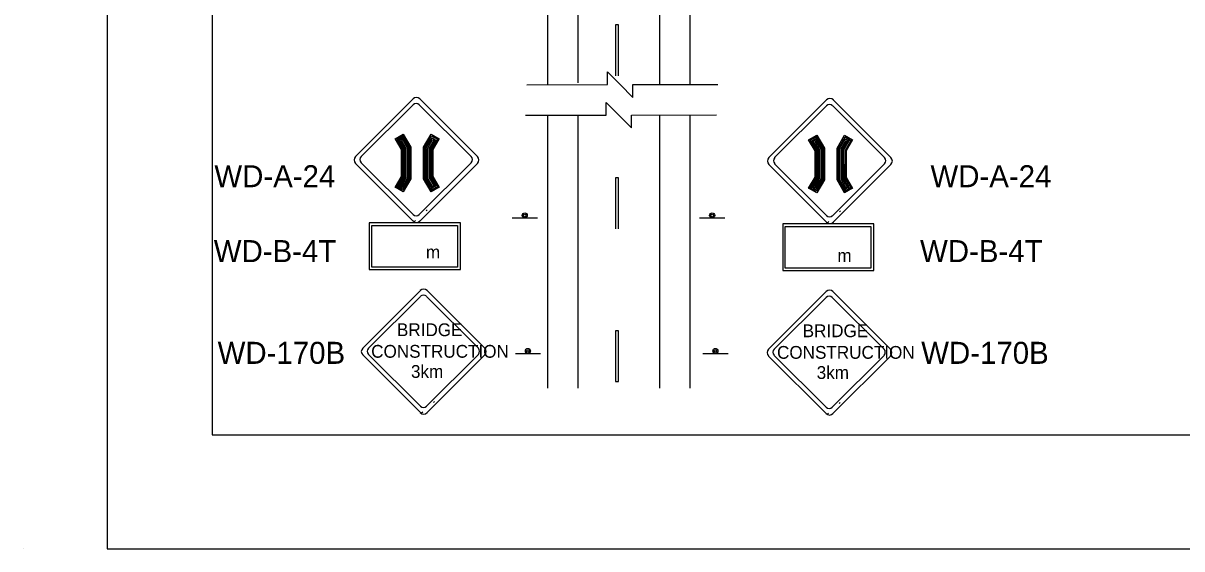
# Model space of a CAD drawing. Extents: x 2171 to 2395, y 134 to 413.
# Drawn here: x 2170.8 to 2280.9, y 133.8 to 183.7 of the extents above; entities that cross this region are included whole.
import ezdxf

# ---------------------------------------------------------------- set-up
doc = ezdxf.new("R2010")
doc.units = 0
for name, color, linetype in [('Level 1', 7, 'Continuous'), ('Level 10', 7, 'Continuous'), ('Level 2', 7, 'Continuous'), ('Level 20', 7, 'Continuous'), ('Level 44', 7, 'Continuous'), ('Level 60', 7, 'Continuous')]:
    doc.layers.add(name, color=color, linetype=linetype)

msp = doc.modelspace()

# ---------------------------------------------------------------- linework, layer by layer
at = {"layer": 'Level 10'}
for p, q in [((2223.52, 177.99), (2223.52, 287.5)), ((2231.26, 177.84), (2231.26, 284.77)), ((2223.52, 149.02), (2223.52, 174.93)), ((2231.26, 149.02), (2231.26, 174.95))]:
    msp.add_line(p, q, dxfattribs=at)
for points in [[(2203.91, 164.47), (2212.05, 164.47), (2212.05, 160.51), (2203.91, 160.51)], [(2243.19, 164.37), (2251.34, 164.37), (2251.34, 160.42), (2243.19, 160.42)]]:
    msp.add_lwpolyline(points, close=True, dxfattribs=at)
at = {"layer": 'Level 2'}
for p, q in [((2227.07, 183.5), (2227.07, 178.66)), ((2227.36, 183.5), (2227.07, 183.5)), ((2227.36, 178.66), (2227.36, 183.5)), ((2227.07, 168.99), (2227.07, 164.15)), ((2227.36, 168.99), (2227.07, 168.99)), ((2227.36, 164.15), (2227.36, 168.99)), ((2209.17, 165.95), (2209.07, 165.85)), ((2248.45, 165.86), (2248.35, 165.75)), ((2208.05, 164.94), (2207.95, 164.83)), ((2247.34, 164.84), (2247.23, 164.73)), ((2227.07, 154.47), (2227.07, 149.64)), ((2227.36, 154.47), (2227.07, 154.47)), ((2227.36, 149.64), (2227.36, 154.47)), ((2227.07, 149.64), (2227.36, 149.64)), ((2209.86, 147.76), (2209.76, 147.66)), ((2248.41, 147.66), (2248.31, 147.56)), ((2208.75, 146.74), (2208.64, 146.64)), ((2247.3, 146.65), (2247.2, 146.54))]:
    msp.add_line(p, q, dxfattribs=at)
at = {"layer": 'Level 20'}
for p, q in [((2234.16, 177.84), (2234.16, 327.61)), ((2220.62, 177.82), (2220.62, 313.63)), ((2220.62, 149.02), (2220.62, 174.93)), ((2234.16, 149.02), (2234.16, 174.95))]:
    msp.add_line(p, q, dxfattribs=at)
for points in [[(2218.63, 177.82), (2226.29, 177.83), (2226.29, 179.04), (2227.5, 177.83), (2228.72, 176.62), (2228.71, 177.83), (2236.79, 177.85)], [(2218.51, 174.93), (2226.17, 174.94), (2226.17, 176.15), (2227.38, 174.94), (2228.59, 173.73), (2228.59, 174.94), (2236.66, 174.96)]]:
    msp.add_lwpolyline(points, dxfattribs=at)
at = {"layer": 'Level 44'}
for p, q in [((2207.83, 176.47), (2202.35, 171)), ((2213.95, 171), (2208.48, 176.47)), ((2247.11, 176.38), (2241.64, 170.91)), ((2253.23, 170.91), (2247.76, 176.38)), ((2202.9, 171), (2207.83, 175.92)), ((2208.41, 175.92), (2213.34, 171)), ((2242.18, 170.9), (2247.11, 175.83)), ((2247.7, 175.83), (2252.62, 170.9)), ((2202.35, 170.35), (2207.83, 164.88)), ((2202.36, 170.35), (2202.35, 170.35)), ((2207.83, 165.49), (2202.9, 170.42)), ((2213.34, 170.42), (2208.41, 165.49)), ((2208.48, 164.88), (2213.95, 170.35)), ((2241.64, 170.26), (2247.11, 164.78)), ((2241.64, 170.26), (2241.64, 170.26)), ((2247.11, 165.39), (2242.18, 170.32)), ((2252.62, 170.32), (2247.7, 165.39)), ((2247.76, 164.78), (2253.23, 170.26)), ((2219.64, 165.15), (2217.24, 165.15)), ((2237.46, 165.15), (2235.06, 165.15)), ((2208.52, 158.28), (2203.05, 152.81)), ((2203.59, 152.81), (2208.52, 157.73)), ((2209.11, 157.73), (2214.03, 152.81)), ((2214.64, 152.81), (2209.17, 158.28)), ((2247.07, 158.18), (2241.6, 152.71)), ((2242.14, 152.71), (2247.07, 157.63)), ((2247.66, 157.63), (2252.58, 152.71)), ((2253.19, 152.71), (2247.72, 158.18)), ((2203.05, 152.16), (2208.52, 146.69)), ((2203.05, 152.16), (2203.05, 152.16)), ((2208.52, 147.3), (2203.59, 152.22)), ((2214.03, 152.22), (2209.11, 147.3)), ((2209.17, 146.69), (2214.64, 152.16)), ((2219.94, 152.27), (2217.55, 152.27)), ((2237.76, 152.27), (2235.36, 152.27)), ((2241.6, 152.06), (2247.07, 146.59)), ((2241.6, 152.06), (2241.6, 152.06)), ((2247.07, 147.2), (2242.14, 152.12)), ((2252.58, 152.12), (2247.66, 147.2)), ((2247.72, 146.59), (2253.19, 152.06))]:
    msp.add_line(p, q, dxfattribs=at)
for points in [[(2206.13, 168.09), (2206.73, 169.13), (2206.73, 171.65), (2206.13, 172.69), (2206.9, 173.14), (2207.62, 171.89), (2207.62, 168.89), (2206.9, 167.65), (2206.13, 168.09), (2206.28, 168.13), (2206.84, 169.1), (2206.84, 171.68), (2206.28, 172.65), (2206.86, 172.99), (2207.51, 171.87), (2207.51, 168.92), (2206.86, 167.8), (2206.28, 168.13), (2206.43, 168.17), (2206.95, 169.07), (2206.95, 171.71), (2206.43, 172.61), (2206.82, 172.83), (2207.4, 171.83), (2207.4, 168.95), (2206.82, 167.95), (2206.43, 168.17), (2206.58, 168.21), (2207.07, 169.04), (2207.06, 171.74), (2206.58, 172.57), (2206.78, 172.69), (2207.29, 171.8), (2207.29, 168.98), (2206.77, 168.09), (2206.58, 168.21), (2206.73, 168.25), (2206.83, 168.2), (2206.73, 168.25), (2207.17, 169.01), (2207.18, 171.77), (2206.73, 172.53), (2206.83, 172.59), (2206.9, 173.14)], [(2209.54, 167.65), (2208.82, 168.89), (2208.82, 171.89), (2209.54, 173.14), (2210.31, 172.69), (2209.71, 171.65), (2209.71, 169.13), (2210.31, 168.09), (2209.54, 167.65), (2209.58, 167.82), (2208.95, 168.92), (2208.95, 171.85), (2209.59, 172.96), (2210.14, 172.64), (2209.58, 171.68), (2209.58, 169.1), (2210.14, 168.14), (2209.58, 167.82), (2209.63, 167.99), (2209.07, 168.96), (2209.07, 171.82), (2209.64, 172.78), (2209.96, 172.59), (2209.46, 171.72), (2209.46, 169.06), (2209.96, 168.19), (2209.63, 167.99), (2209.68, 168.17), (2209.21, 168.99), (2209.21, 171.78), (2209.68, 172.61), (2209.79, 172.55), (2209.32, 171.75), (2209.33, 169.03), (2209.79, 168.23), (2209.68, 168.17), (2210.31, 168.09)], [(2245.41, 168), (2246.02, 169.03), (2246.02, 171.56), (2245.41, 172.59), (2246.18, 173.04), (2246.91, 171.79), (2246.91, 168.8), (2246.18, 167.55), (2245.41, 168), (2245.56, 168.03), (2246.12, 169.01), (2246.13, 171.58), (2245.56, 172.55), (2246.14, 172.89), (2246.8, 171.77), (2246.8, 168.82), (2246.14, 167.7), (2245.56, 168.03), (2245.72, 168.08), (2246.23, 168.97), (2246.24, 171.61), (2245.72, 172.51), (2246.1, 172.73), (2246.68, 171.73), (2246.68, 168.85), (2246.1, 167.85), (2245.72, 168.08), (2245.86, 168.11), (2246.35, 168.94), (2246.34, 171.64), (2245.86, 172.47), (2246.06, 172.59), (2246.57, 171.71), (2246.57, 168.88), (2246.05, 168), (2245.86, 168.11), (2246.02, 168.16), (2246.12, 168.1), (2246.02, 168.16), (2246.45, 168.91), (2246.46, 171.67), (2246.02, 172.43), (2246.12, 172.49), (2246.18, 173.04)], [(2248.83, 167.55), (2248.11, 168.8), (2248.11, 171.79), (2248.83, 173.04), (2249.59, 172.59), (2248.99, 171.56), (2248.99, 169.03), (2249.59, 168), (2248.83, 167.55), (2248.87, 167.72), (2248.23, 168.83), (2248.24, 171.76), (2248.87, 172.86), (2249.42, 172.54), (2248.87, 171.58), (2248.86, 169), (2249.42, 168.04), (2248.87, 167.72), (2248.91, 167.9), (2248.36, 168.86), (2248.36, 171.72), (2248.92, 172.69), (2249.24, 172.5), (2248.74, 171.62), (2248.74, 168.97), (2249.24, 168.09), (2248.91, 167.9), (2248.96, 168.07), (2248.49, 168.9), (2248.49, 171.69), (2248.97, 172.51), (2249.07, 172.45), (2248.61, 171.65), (2248.61, 168.93), (2249.07, 168.13), (2248.96, 168.07), (2249.59, 168)]]:
    msp.add_lwpolyline(points, dxfattribs=at)
for points in [[(2212.33, 164.7), (2203.67, 164.7), (2203.67, 160.27), (2212.33, 160.27)], [(2251.61, 164.6), (2242.95, 164.6), (2242.95, 160.17), (2251.61, 160.17)]]:
    msp.add_lwpolyline(points, close=True, dxfattribs=at)
for centre, radius in [((2218.44, 165.41), 0.24), ((2218.44, 165.41), 0.12), ((2236.25, 165.41), 0.24), ((2236.25, 165.41), 0.12), ((2218.74, 152.54), 0.24), ((2218.74, 152.54), 0.12), ((2236.55, 152.54), 0.24), ((2236.55, 152.54), 0.12)]:
    msp.add_circle(centre, radius, dxfattribs=at)
for centre, radius, start, end in [((2208.15, 176.15), 0.458, 45, 135), ((2247.44, 176.06), 0.458, 45, 135), ((2208.12, 175.63), 0.412, 45, 135), ((2247.4, 175.54), 0.412, 45, 135), ((2202.68, 170.68), 0.458, 135, 225), ((2203.19, 170.71), 0.412, 135, 225), ((2213.05, 170.71), 0.412, 315, 45), ((2213.63, 170.68), 0.458, 315, 45), ((2241.96, 170.58), 0.458, 135, 225), ((2242.48, 170.61), 0.412, 135, 225), ((2252.33, 170.61), 0.412, 315, 45), ((2252.91, 170.58), 0.458, 315, 45), ((2208.12, 165.78), 0.412, 225, 315), ((2247.4, 165.69), 0.412, 225, 315), ((2208.15, 165.21), 0.458, 225, 315), ((2247.44, 165.11), 0.458, 225, 315), ((2208.84, 157.96), 0.458, 45, 135), ((2208.81, 157.44), 0.412, 45, 135), ((2247.4, 157.86), 0.458, 45, 135), ((2247.36, 157.34), 0.412, 45, 135), ((2203.37, 152.49), 0.458, 135, 225), ((2203.89, 152.51), 0.412, 135, 225), ((2213.74, 152.51), 0.412, 315, 45), ((2214.32, 152.49), 0.458, 315, 45), ((2241.92, 152.39), 0.458, 135, 225), ((2242.44, 152.42), 0.412, 135, 225), ((2252.29, 152.42), 0.412, 315, 45), ((2252.87, 152.39), 0.458, 315, 45), ((2208.81, 147.59), 0.412, 225, 315), ((2208.84, 147.01), 0.458, 225, 315), ((2247.36, 147.49), 0.412, 225, 315), ((2247.4, 146.92), 0.458, 225, 315)]:
    msp.add_arc(centre, radius, start, end, dxfattribs=at)
at = {"layer": 'Level 60'}
for p, q in [((2188.75, 144.57), (2188.75, 144.57)), ((2170.78, 133.76), (2170.78, 133.76))]:
    msp.add_line(p, q, dxfattribs=at)
for points in [[(2394.75, 412.76), (2178.75, 412.76), (2178.75, 133.76), (2394.75, 133.76)], [(2375.62, 401.95), (2188.75, 401.95), (2188.75, 144.57), (2375.62, 144.57)]]:
    msp.add_lwpolyline(points, close=True, dxfattribs=at)

# ---------------------------------------------------------------- texts
at = {"layer": 'Level 1'}
for p in [(2188.89, 160.98), (2256, 160.98)]:
    msp.add_text('WD-B-4T', height=2.09, dxfattribs=at).set_placement(p)
at = {"layer": 'Level 10'}
for s, p in [('WD-A-24', (2188.95, 168.09)), ('WD-A-24', (2256.99, 168.09)), ('WD-170B', (2189.26, 151.32)), ('WD-170B', (2256.11, 151.32))]:
    msp.add_text(s, height=2.09, dxfattribs=at).set_placement(p)
at = {"layer": 'Level 44'}
for s, height, p in [('m', 1.21, (2209.05, 161.33)), ('m', 1.21, (2248.15, 161)), ('CONSTRUCTION', 1.2143, (2203.85, 151.9)), ('CONSTRUCTION', 1.2143, (2242.41, 151.8)), ('3km', 1.214, (2207.63, 149.99)), ('3km', 1.214, (2246.18, 149.89))]:
    msp.add_text(s, height=height, dxfattribs=at).set_placement(p)
for p in [(2206.3, 153.95), (2244.85, 153.85)]:
    msp.add_text('BRIDGE', height=1.214, rotation=360, dxfattribs=at).set_placement(p)

doc.saveas('drawing.dxf')
